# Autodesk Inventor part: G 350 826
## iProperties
Company: Mayer & Müller AG Schaltgeräte
Created: 2005-12
Part Number: G 350 826
Material: 2.0060.26
Document SubType Name: Modeling
Designer: I.Baliuc
Manufacturer: Standard
Standards Organization: Custom
Description: Stromschiene, oben
Density: 8.94 g/cm^3
HalbzeugNorm: DIN 1759
Zweck: für Festeinbau
Abmessung: Fl. 80 x 15 -160
Author: T.Messerschmitt
Revision Number: 350826
Keywords: 382022
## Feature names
1. Extrusion2
2. Bohrung1 [Hole]
3. Bohrung2 [Hole]
4. Bohrung3 [Hole]
